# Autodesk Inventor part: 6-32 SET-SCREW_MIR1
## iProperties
Created: 2007-08
Part Number: 6-32 SET-SCREW_MIR1
Document SubType Name: Modeling
Mass: 0.0379541 g
Surface Area: 1.01226 cm^2
Volume: 0.0379541 cm^3
Density: 1 g/cm^3
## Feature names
1. Derived Body1 [Tagging]
